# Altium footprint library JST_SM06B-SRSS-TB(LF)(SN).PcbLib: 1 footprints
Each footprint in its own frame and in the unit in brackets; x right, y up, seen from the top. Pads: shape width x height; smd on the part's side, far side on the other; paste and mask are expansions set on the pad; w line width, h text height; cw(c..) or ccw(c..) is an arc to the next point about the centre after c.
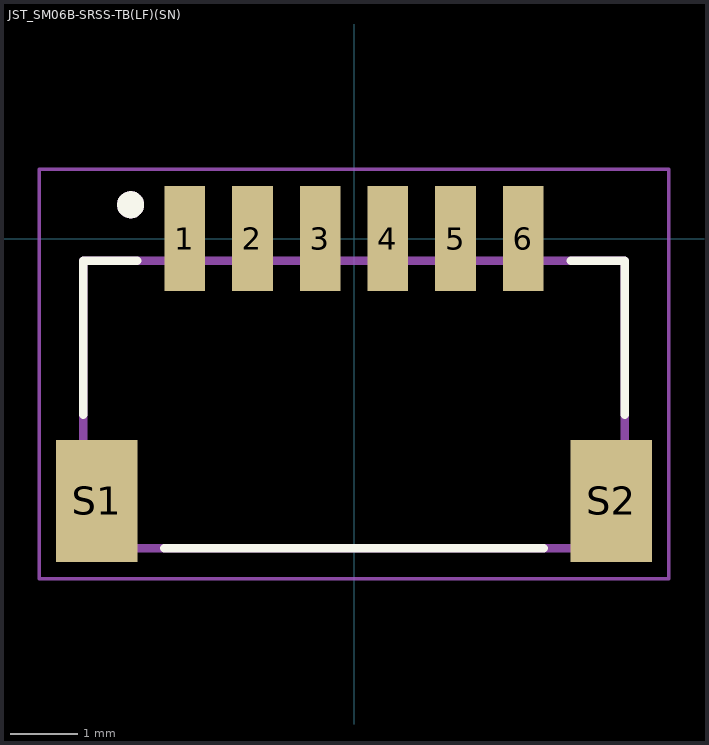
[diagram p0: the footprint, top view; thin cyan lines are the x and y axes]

## JST_SM06B-SRSS-TB(LF)(SN) [mm]
pads (8):
  rect 0.6x1.55 smd: 1(-2.5,0) 2(-1.5,0) 3(-0.5,0) 4(0.5,0) 5(1.5,0) 6(2.5,0)
  rect 1.2x1.8 smd: S1(-3.8,-3.875) S2(3.8,-3.875)
Top Overlay:
  circle w0.2: c-3.3,0.5 r0.1
  lines w0.127: -4,-2.6 -4,-0.325 -3.2,-0.325 ; -2.8,-4.575 2.8,-4.575 ; 3.2,-0.325 4,-0.325 4,-2.6
Assembly Top:
  circle w0.2: c-3.3,0.5 r0.1
  lines w0.127: -4,-4.575 4,-4.575 4,-0.325 -4,-0.325 -4,-4.575
Courtyard Top:
  lines w0.05: -4.65,-5.025 4.65,-5.025 4.65,1.025 -4.65,1.025 -4.65,-5.025
3D body "step_temp.STEP": height 2.95, standoff 0, extent -4,-4.572 4,0.378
